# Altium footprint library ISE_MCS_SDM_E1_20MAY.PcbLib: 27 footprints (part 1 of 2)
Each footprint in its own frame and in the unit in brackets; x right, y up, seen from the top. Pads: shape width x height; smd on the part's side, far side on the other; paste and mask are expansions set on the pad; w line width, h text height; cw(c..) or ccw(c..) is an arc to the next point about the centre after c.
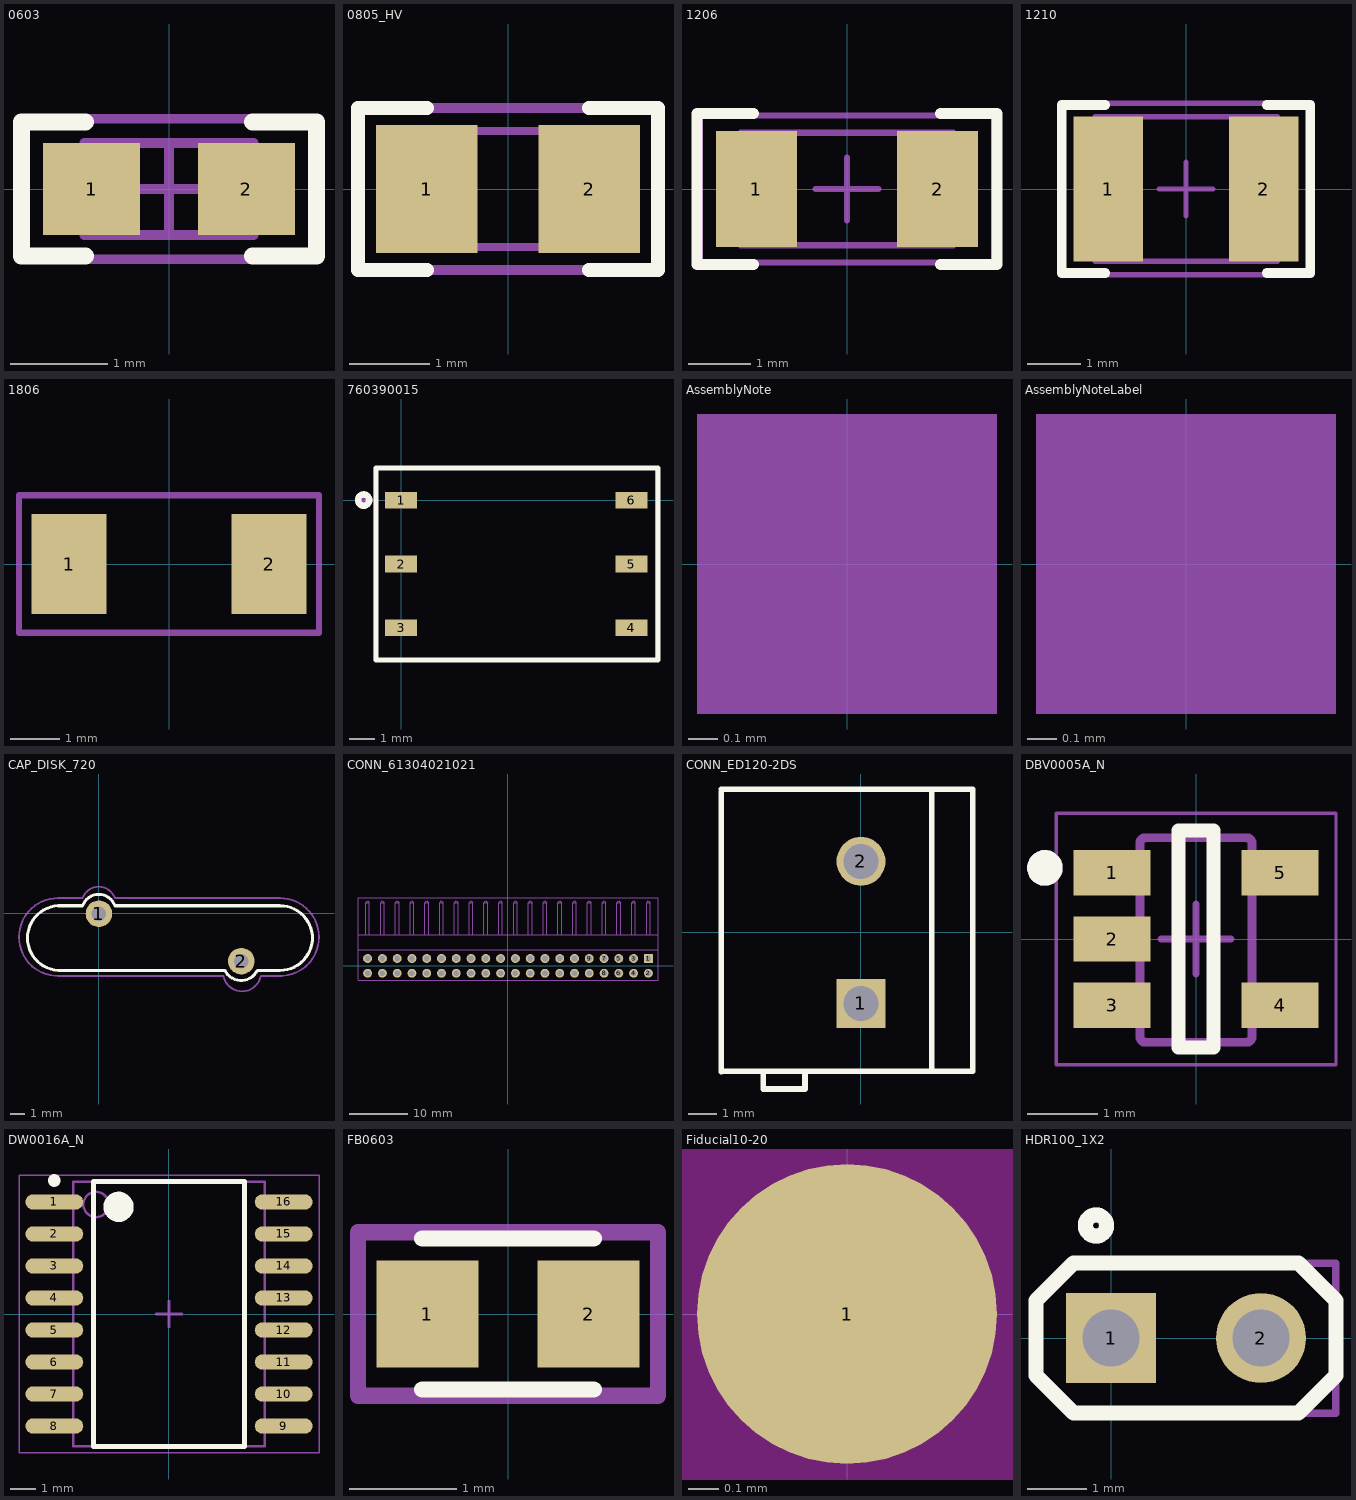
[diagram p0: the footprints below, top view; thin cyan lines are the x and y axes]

## 0603 [mm] "0603 from SM-752 data"
height 0.85
pads (2):
  rect 1x0.95 smd: 1(-0.8,0) 2(0.8,0)
Top Overlay:
  lines w0.178: -0.864,-0.691 -1.524,-0.691 -1.524,0.693 -0.864,0.693 ; 0.864,-0.691 1.524,-0.691 1.524,0.693 0.864,0.693
Mechanical 5:
  lines w0.1: -1.55,-0.725 -1.55,0.725 1.55,0.725 1.55,-0.725 -1.55,-0.725
  text ".Designator" at -1.397,-0.381 h0.76
Mechanical 13:
  lines w0.1: -0.55,-0.475 -0.55,0.475 ; 0.55,-0.475 0.55,0.475 ; -0.875,-0.475 0.875,-0.475 0.875,0.475 -0.875,0.475 -0.875,-0.475
Mechanical 15:
  lines w0.1: -0.475,0 0.475,0 ; 0,-0.475 0,0.475 ; -1.55,-0.725 1.55,-0.725 1.55,0.725 -1.55,0.725 -1.55,-0.725
3D body: height 0.85, standoff 0, extent -0.874,-0.474 -0.551,0.474
3D body: height 0.85, standoff 0, extent -0.549,-0.474 0.549,0.474
3D body: height 0.85, standoff 0, extent 0.551,-0.474 0.874,0.474

## 0805_HV [mil] "0805 with 30mil clearance between pads"
height 43.31
pads (2):
  rect 50x63 smd: 1(-40,0) 2(40,0)
Top Overlay:
  lines w7: -40,-40 -74,-40 -74,0 -74,40 -40,40 ; 40,-40 74,-40 74,0 74,40 40,40
Mechanical 5:
  lines w5: -74,-40 -74,40 74,40 74,-40 -74,-40
  text ".Designator" at -64,-17 h35
Mechanical 13:
  lines w3.94: -25.59,-28.54 -25.59,28.54 ; 25.59,-28.54 25.59,28.54 ; -43.31,-28.54 43.31,-28.54 43.31,28.54 -43.31,28.54 -43.31,-28.54
3D body: height 43.31, standoff 0, extent -43.29,-28.52 -25.61,28.52
3D body: height 43.31, standoff 0, extent -25.57,-28.52 25.57,28.52
3D body: height 43.31, standoff 0, extent 25.61,-28.52 43.29,28.52

## 1206 [mm] "1206 from SM-752 data"
height 1.35
pads (2):
  rect 1.3x1.85 smd: 1(-1.45,0) 2(1.45,0)
Top Overlay:
  lines w0.178: -1.5,-1.21 -2.4,-1.21 -2.4,1.21 -1.5,1.21 ; 1.5,-1.21 2.4,-1.21 2.4,1.21 1.5,1.21
Mechanical 5:
  lines w0.1: -1.7,-0.9 1.7,-0.9 1.7,0.9 -1.7,0.9 -1.7,-0.9
  text ".Designator" at -1.475,-0.4 h0.81
Mechanical 13:
  lines w0.1: -1.2,-0.9 -1.2,0.9 ; 1.2,-0.9 1.2,0.9 ; -1.7,-0.9 1.7,-0.9 1.7,0.9 -1.7,0.9 -1.7,-0.9
Mechanical 15:
  lines w0.1: -0.5,0 0.5,0 ; 0,-0.5 0,0.5 ; -2.35,-1.175 2.35,-1.175 2.35,1.175 -2.35,1.175 -2.35,-1.175
3D body: height 1.35, standoff 0, extent -1.699,-0.899 -1.201,0.899
3D body: height 1.35, standoff 0, extent -1.199,-0.899 1.199,0.899
3D body: height 1.35, standoff 0, extent 1.201,-0.899 1.699,0.899

## 1210 [mm] "1210 from SM-752 data"
height 1.35
pads (2):
  rect 1.3x2.7 smd: 1(-1.45,0) 2(1.45,0)
Top Overlay:
  lines w0.178: -1.511,-1.568 -2.316,-1.568 -2.316,1.568 -1.511,1.568 ; 1.511,-1.568 2.316,-1.568 2.316,1.568 1.511,1.568
Mechanical 5:
  lines w0.1: -1.7,-1.35 1.7,-1.35 1.7,1.35 -1.7,1.35 -1.7,-1.35
  text ".Designator" at -1.4,-0.375 h0.76
Mechanical 13:
  lines w0.1: -1.2,-1.35 -1.2,1.35 ; 1.2,-1.35 1.2,1.35 ; -1.7,-1.35 -1.7,1.35 1.7,1.35 1.7,-1.35 -1.7,-1.35
Mechanical 15:
  lines w0.1: -0.5,0 0.5,0 ; 0,-0.5 0,0.5 ; -2.35,-1.6 -2.35,1.6 2.35,1.6 2.35,-1.6 -2.35,-1.6
3D body: height 1.35, standoff 0, extent -1.699,-1.349 -1.201,1.349
3D body: height 1.35, standoff 0, extent -1.199,-1.349 1.199,1.349
3D body: height 1.35, standoff 0, extent 1.201,-1.349 1.699,1.349

## 1806 [mil]
pads (2):
  rect 60x80 smd mask+2: 1(-80,0) 2(80,0)
Mechanical 5:
  lines w5: -120,-55 120,-55 120,55 -120,55 -120,-55
  text ".Designator" at -73,-20 h40

## 760390015 [mm]
pads (6):
  rect 1.27x0.66 smd: 1(0,0) 2(0,-2.54) 3(0,-5.08) 4(9.14,-5.08) 5(9.14,-2.54) 6(9.14,0)
Top Overlay:
  circle w0.254: c-1.494,0 r0.224
  lines w0.2: -1,-6.35 10.2,-6.35 10.2,1.27 -1,1.27 -1,-6.35
Mechanical 5:
  circle w0.254: c-1.397,0 r0.127
  lines w0.152: -1.016,-6.35 -1.016,1.27 10.16,1.27 10.16,-6.35 -1.016,-6.35
  text ".designator" at 1.397,-3.429 h1.52
3D body: height 4.2, standoff 0.2, extent -1,-6.4 10.2,1.2

## AssemblyNote [mil] "Assembly Note"
Mechanical 5:
  rectangle: -20,-20 20,20
  text ".Comment" at 45,-20 h40
  text ".Designator" at -174.37,-23.77 h40

## AssemblyNoteLabel [mil] "Assembly Note for PCB Labels"
Mechanical 5:
  rectangle: -20,-20 20,20
  text "Install label in silkscreened box after final wash.  Text shall be 8 pt font.  Text shall be per the Label Table in the PDF schematic." at 45,-20 h40
  text ".Designator" at -189.37,-24.77 h40

## CAP_DISK_720 [mil]
pads (2):
  round 70 hole 38: 1(0,-1) 2(375,-126)
Top Overlay:
  lines w8: -98,-150 332,-150 ccw(c374.5,-130) 417,-150 477,-150 ccw(c477,-65) 477,20 42,20 ; -98,20 -43,20 ; -97.95,-150 cw(c-103,-65) -97.95,20 ; -43.01,19.97 cw(c-0.5,5) 42.01,19.97
Mechanical 5:
  lines w5: -43.01,39.97 cw(c-0.5,25) 42.01,39.97 ; -43,40 -108,40 ccw(c-108,-62.5) -108,-165 327,-165 ; 42,40 477,40 cw(c477,-62.5) 477,-165 ; 327.72,-164.85 ccw(c377,-155) 426.28,-164.85 ; 427,-165 482,-165
  text ".Designator" at 150,-377 h60

## CONN_61304021021 [mil]
pads (40):
  rect 60x60 hole 38: 1(952,50)
  round 60 hole 38: 2(952,-50) 3(852,50) 4(852,-50) 5(752,50) 6(752,-50) 7(652,50) 8(652,-50) 9(552,50) 10(552,-50) 11(452,50) 12(452,-50) 13(352,50) 14(352,-50) 15(252,50) 16(252,-50) 17(152,50) 18(152,-50) 19(52,50) 20(52,-50) 21(-48,50) 22(-48,-50) 23(-148,50) 24(-148,-50) 25(-248,50) 26(-248,-50) 27(-348,50) 28(-348,-50) 29(-448,50) 30(-448,-50) 31(-548,50) 32(-548,-50) 33(-648,50) 34(-648,-50) 35(-748,50) 36(-748,-50) 37(-848,50) 38(-848,-50) 39(-948,50) 40(-948,-50)
Mechanical 5:
  lines w5: -1013,109.5 1017,109.5 ; -1013,209.5 1017,209.5 ; -1013,-95.5 1017,-95.5 1017,459.5 -1013,459.5 -1013,-95.5
  text ".Designator" at -73,-20 h40
Mechanical 16:
  lines w1: -960.5,210 -960.5,427.5 ; -935.5,210 -935.5,427.5 ; -860.5,210 -860.5,427.5 ; -835.5,210 -835.5,427.5 ; -760.5,210 -760.5,427.5 ; -735.5,210 -735.5,427.5 ; -660.5,210 -660.5,427.5 ; -635.5,210 -635.5,427.5 ; -560.5,210 -560.5,427.5 ; -535.5,210 -535.5,427.5 ; -460.5,210 -460.5,427.5 ; -435.5,210 -435.5,427.5 ; -360.5,210 -360.5,427.5 ; -335.5,210 -335.5,427.5 ; -260.5,210 -260.5,427.5 ; -235.5,210 -235.5,427.5 ; -160.5,210 -160.5,427.5 ; -135.5,210 -135.5,427.5 ; -60.5,210 -60.5,427.5 ; -35.5,210 -35.5,427.5 ; 39.5,210 39.5,427.5 ; 64.5,210 64.5,427.5 ; 139.5,210 139.5,427.5 ; 164.5,210 164.5,427.5 ; 239.5,210 239.5,427.5 ; 264.5,210 264.5,427.5 ; 339.5,210 339.5,427.5 ; 364.5,210 364.5,427.5 ; 439.5,210 439.5,427.5 ; 464.5,210 464.5,427.5 ; 539.5,210 539.5,427.5 ; 564.5,210 564.5,427.5 ; 639.5,210 639.5,427.5 ; 664.5,210 664.5,427.5 ; 739.5,210 739.5,427.5 ; 764.5,210 764.5,427.5 ; 839.5,210 839.5,427.5 ; 864.5,210 864.5,427.5 ; 939.5,210 939.5,427.5 ; 964.5,210 964.5,427.5 ; -960.5,427.5 -948,440 -935.5,427.5 ; -960.5,427.5 -935.5,427.5 ; -860.5,427.5 -835.5,427.5 ; -860.5,427.5 -848,440 -835.5,427.5 ; -760.5,427.5 -748,440 -735.5,427.5 ; -760.5,427.5 -735.5,427.5 ; -660.5,427.5 -648,440 -635.5,427.5 ; -660.5,427.5 -635.5,427.5 ; -560.5,427.5 -548,440 -535.5,427.5 ; -560.5,427.5 -535.5,427.5 ; -460.5,427.5 -435.5,427.5 ; -460.5,427.5 -448,440 -435.5,427.5 ; -360.5,427.5 -348,440 -335.5,427.5 ; -360.5,427.5 -335.5,427.5 ; -260.5,427.5 -248,440 -235.5,427.5 ; -260.5,427.5 -235.5,427.5 ; -160.5,427.5 -148,440 -135.5,427.5 ; -160.5,427.5 -135.5,427.5 ; -60.5,427.5 -48,440 -35.5,427.5 ; -60.5,427.5 -35.5,427.5 ; 39.5,427.5 64.5,427.5 ; 39.5,427.5 52,440 64.5,427.5 ; 139.5,427.5 164.5,427.5 ; 139.5,427.5 152,440 164.5,427.5 ; 239.5,427.5 264.5,427.5 ; 239.5,427.5 252,440 264.5,427.5 ; 339.5,427.5 352,440 364.5,427.5 ; 339.5,427.5 364.5,427.5 ; 439.5,427.5 452,440 464.5,427.5 ; 439.5,427.5 464.5,427.5 ; 539.5,427.5 552,440 564.5,427.5 ; 539.5,427.5 564.5,427.5 ; 639.5,427.5 652,440 664.5,427.5 ; 639.5,427.5 664.5,427.5 ; 739.5,427.5 752,440 764.5,427.5 ; 739.5,427.5 764.5,427.5 ; 839.5,427.5 852,440 864.5,427.5 ; 839.5,427.5 864.5,427.5 ; 939.5,427.5 952,440 964.5,427.5 ; 939.5,427.5 964.5,427.5

## CONN_ED120-2DS [mm] "ONSHORE"
height 13
pads (2):
  rect 1.75x1.75 hole 1.25: 1(0,-2.54)
  round 1.75 hole 1.25: 2(0,2.54)
Top Overlay:
  lines w0.2: -5,-4.985 -5,5.015 ; -5,-4.96 4,-4.96 ; -5,5.115 4,5.115 4,-4.885 ; -3.5,-4.96 -3.5,-5.6 -2,-5.6 -2,-4.96 ; 2.525,-4.95 2.525,5.05
Mechanical 5:
  lines w0.1: -5,-4.96 4,-4.96 ; -5,-4.885 -5,5.115 4,5.115 4,-4.885 ; -3.5,-4.96 -3.5,-5.6 -2,-5.6 -2,-4.96 ; 2.525,-4.875 2.525,5.125
  text ".Designator" at -2.75,-0.4 h1.02
3D body: height 13, standoff 0, extent -5,-4.985 4,5.115
3D body: height 13.1, standoff -2.5, extent -0.496,-3.039 0.5,-2.041
3D body: height 13.1, standoff -2.5, extent -0.496,2.041 0.5,3.039
3D body: height 5.7, standoff 4.3, extent -0.85,1.846 4.15,3.24
3D body: height 5.7, standoff 4.3, extent -0.875,-3.204 4.125,-1.81
3D body: height 13, standoff 0, extent -3.5,-5.6 -2,-4.925

## DBV0005A_N [mm] "SOT23, 5-Leads, Body 2.9x1.6mm, Pitch 0.95mm, Lead Span 2.8mm, IPC Medium Density"
height 1.45
pads (5):
  rect 1.1x0.65 smd: 1(-1.2,0.95) 2(-1.2,0) 3(-1.2,-0.95) 4(1.2,-0.95) 5(1.2,0.95)
Top Overlay:
  circle w0.254: c-2.159,1.016 r0.127
  lines w0.2: -0.25,-1.55 0.25,-1.55 0.25,1.55 -0.25,1.55 -0.25,-1.55
Mechanical 5:
  circle w0.254: c-2.159,1.016 r0.127
  lines w0.127: -0.801,1.371 cw(c-0.725,1.37) -0.725,1.446 ; -0.801,1.37 -0.801,-1.399 -0.801,-1.4 ccw(c-0.725,-1.399) -0.725,-1.475 ; -0.801,1.37 -0.801,1.371 ; -0.725,-1.475 -0.725,-1.475 ; -0.725,-1.475 0.723,-1.475 0.724,-1.475 ccw(c0.723,-1.399) 0.799,-1.4 0.799,-1.399 0.799,1.37 ; -0.725,1.446 0.723,1.446 0.724,1.446 cw(c0.723,1.37) 0.799,1.371 ; -0.725,1.446 -0.725,1.446 ; 0.799,1.37 0.799,1.371 ; -1.423,-1.167 -1.199,-1.167 -1.105,-1.167 -1.088,-1.167 -0.835,-1.167 -0.801,-1.167 -0.801,-0.767 -0.835,-0.767 -1.088,-0.767 -1.105,-0.767 -1.199,-0.767 -1.423,-0.767 -1.423,-1.167 ; -1.423,-0.215 -1.199,-0.215 -1.105,-0.215 -1.088,-0.215 -0.835,-0.215 -0.801,-0.215 -0.801,0.186 -0.835,0.186 -1.088,0.186 -1.105,0.186 -1.199,0.186 -1.423,0.186 -1.423,-0.215 ; -1.423,0.738 -1.199,0.738 -1.105,0.738 -1.088,0.738 -0.835,0.738 -0.801,0.738 -0.801,1.138 -0.835,1.138 -1.088,1.138 -1.105,1.138 -1.199,1.138 -1.423,1.138 -1.423,0.738 ; 0.799,-1.167 0.799,-0.767 0.834,-0.767 1.087,-0.767 1.103,-0.767 1.198,-0.767 1.422,-0.767 1.422,-1.167 1.198,-1.167 1.103,-1.167 1.087,-1.167 0.834,-1.167 0.799,-1.167 ; 0.799,0.738 0.799,1.138 0.834,1.138 1.087,1.138 1.103,1.138 1.198,1.138 1.422,1.138 1.422,0.738 1.198,0.738 1.103,0.738 1.087,0.738 0.834,0.738 0.799,0.738
  text ".Designator" at -0.25,0.95 h0.51
Mechanical 15:
  lines w0.05: -2,-1.8 -2,1.8 2,1.8 2,-1.8 -2,-1.8
  lines w0.1: -0.5,0 0.5,0 ; 0,-0.5 0,0.5
3D body: height 1.08, standoff -0.01, extent -1.422,-1.461 1.422,1.46

## DW0016A_N [mm] "SOIC, 16-Leads, Body 10.3x7.5mm, Pitch 1.27mm, IPC Medium Density"
height 2.64
pads (16):
  oval 2.3x0.6 smd: 1(-4.55,4.445) 2(-4.55,3.175) 3(-4.55,1.905) 4(-4.55,0.635) 5(-4.55,-0.635) 6(-4.55,-1.905) 7(-4.55,-3.175) 8(-4.55,-4.445) 9(4.55,-4.445) 10(4.55,-3.175) 11(4.55,-1.905) 12(4.55,-0.635) 13(4.55,0.635) 14(4.55,1.905) 15(4.55,3.175) 16(4.55,4.445)
Top Overlay:
  circle w0.25: c-4.55,5.295 r0.125
  circle w0.6: c-2,4.25 r0.3
  lines w0.2: -3,-5.25 -3,5.25 3,5.25 3,-5.25 -3,-5.25
Mechanical 5:
  circle w0.1: c-2.895,4.345 r0.5
  lines w0.1: -3.795,-5.245 -3.795,5.245 3.795,5.245 3.795,-5.245 -3.795,-5.245
  text ".Designator" at -1.854,-0.508 h1.02
Mechanical 15:
  lines w0.05: -5.95,-5.5 -5.95,5.5 5.95,5.5 5.95,-5.5 -5.95,-5.5
  lines w0.1: -0.5,0 0.5,0 ; 0,-0.5 0,0.5
3D body: height 2.64, standoff 0.1, extent -3.795,-5.245 3.795,5.245

## FB0603 [mm]
height 0.95
pads (2):
  rect 0.95x1 smd: 1(-0.75,0) 2(0.75,0)
Top Overlay:
  lines w0.152: -0.8,-0.703 0.8,-0.703 ; -0.8,0.703 0.8,0.703
Mechanical 5:
  lines w0.152: -1.397,-0.762 1.397,-0.762 1.397,0.127 1.397,0.762 -1.397,0.762 -1.397,-0.762
  text ".designator" at -1.143,-0.381 h1.52
Mechanical 15:
  lines w0.025: -0.8,-0.4 -0.8,0.4 ; 0.8,-0.4 0.8,0.4
  lines w0.1: -0.8,-0.4 -0.8,0.4

## Fiducial10-20 [mm]
pads (1):
  round 1 smd paste-0.5 mask+0.5: 1(0,0)
Top Layer keep-out:
  circle w1.178: c0,0 r0.5

## HDR100_1X2 [mil]
pads (2):
  rect 60x60 hole 38: 1(0,0)
  round 60 hole 38: 2(100,0)
Top Overlay:
  circle w10: c-10,75 r7.07
  lines w10: -50,-25 -25,-50 125,-50 150,-25 150,25 125,50 -25,50 -50,25 -50,-25
Mechanical 5:
  circle w10: c-10,75 r7.07
  lines w5: -50,-25 -50,25 -25,50 150,50 150,-50 -25,-50 -50,-25
  text ".Designator" at -29,-12 h40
